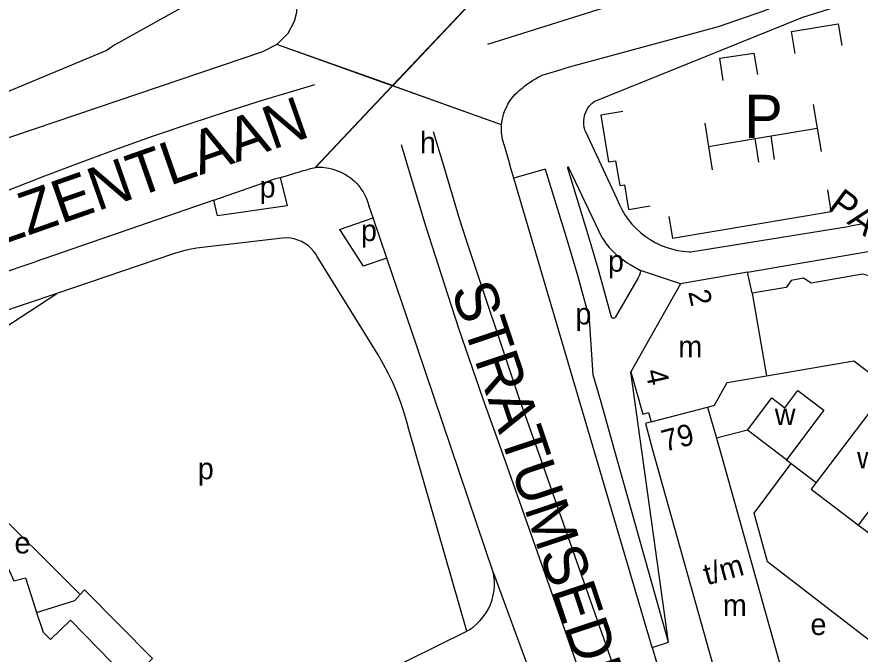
# Model space of a CAD drawing. Extents: x 161141 to 163125, y 381621 to 383200.
# Drawn here: x 161806 to 161962.7, y 382212.1 to 382330.5 of the extents above; entities that cross this region are included whole.
import ezdxf

# ---------------------------------------------------------------- set-up
doc = ezdxf.new("R2010")
doc.units = 0
for name, color, linetype in [('BLT_Basislijn', 7, 'Continuous'), ('BLT_Bebouwing', 7, 'Continuous'), ('BLT_Centroide', 7, 'Continuous'), ('BLT_Huisnummer_reeks', 7, 'Continuous'), ('BLT_Onderverdeling_panden', 7, 'Continuous'), ('BLT_Straatnaam', 7, 'Continuous'), ('BLT_Straatnaam_hoofdweg', 7, 'Continuous'), ('BLT_Tekst_parkeren', 7, 'Continuous'), ('BLT_Vlakafsluiter', 7, 'Continuous')]:
    doc.layers.add(name, color=color, linetype=linetype)

msp = doc.modelspace()

# ---------------------------------------------------------------- linework, layer by layer
at = {"layer": 'BLT_Basislijn'}
for p, q in [((161940.18, 382340.08), (161893.48, 382325.35)), ((161906.53, 382320.54), (161908.69, 382321.22)), ((161954.02, 382314.18), (161954.76, 382309.78)), ((161933.85, 382310.76), (161934.55, 382306.41)), ((161911.59, 382309.32), (161917.49, 382296.67)), ((161946.18, 382308.35), (161954.76, 382309.78)), ((161954.76, 382309.78), (161955.49, 382305.48)), ((161934.55, 382306.41), (161943.23, 382307.86)), ((161943.23, 382307.86), (161946.18, 382308.35)), ((161943.9, 382303.51), (161943.23, 382307.86)), ((161946.8, 382303.99), (161946.18, 382308.35)), ((161896.48, 382306.85), (161897.6, 382303.01)), ((161934.55, 382306.41), (161935.24, 382302.07)), ((161898.34, 382300.52), (161897.6, 382303.01)), ((161908.3, 382302.46), (161908.31, 382302.41)), ((161904.18, 382302.21), (161898.34, 382300.52)), ((161914.78, 382289.4), (161908.59, 382302.42)), ((161854.91, 382300.62), (161856.21, 382295.39)), ((161924.08, 382213.31), (161898.34, 382300.52)), ((161842.56, 382296.43), (161809.35, 382284.99)), ((161843.29, 382293.52), (161842.56, 382296.43)), ((161856.21, 382295.39), (161843.29, 382293.52)), ((161865.97, 382290.99), (161872.19, 382293.11)), ((161931.22, 382286.81), (161960.87, 382291.6)), ((161963.33, 382292.05), (161960.87, 382291.6)), ((161865.97, 382290.99), (161870.33, 382284.17)), ((161941.81, 382283.04), (161966.62, 382287.31)), ((161874.72, 382285.67), (161870.33, 382284.17)), ((161770.9, 382271.87), (161809.35, 382284.99)), ((161919.97, 382284.49), (161921.9, 382283.36)), ((161929.35, 382280.89), (161921.9, 382283.36)), ((161921.45, 382282), (161917.17, 382274.64)), ((161813.37, 382279.08), (161782.6, 382268.66)), ((161941.76, 382253.66), (161936.01, 382252.18)), ((161949.01, 382248.17), (161949.93, 382247.46)), ((161949.93, 382247.46), (161954.56, 382243.93)), ((161962.44, 382236.04), (161967.99, 382231.82)), ((161924.08, 382213.31), (161927.07, 382214.26))]:
    msp.add_line(p, q, dxfattribs=at)
for points in [[(161908.69, 382321.22), (161936.4, 382328.72), (161945.01, 382331.67), (161952.31, 382334.78), (162029.12, 382358.63), (162066.74, 382371.68)], [(161793.69, 382312.24), (161822.54, 382324.21), (161823.81, 382325.1), (161843.74, 382336.23), (161846.45, 382340.89), (161847.52, 382345.91), (161849.28, 382355.23)], [(161913.27, 382314.74), (161952.05, 382330.4), (162030.21, 382354.86)], [(161854.31, 382325.37), (161856.37, 382327.47), (161857.59, 382329.71), (161858, 382331.34), (161858.1, 382333.18), (161857.49, 382336.44), (161856.39, 382341.05)], [(161950.63, 382323.7), (161949.94, 382327.79), (161958.64, 382329.2), (161959.34, 382325.15)], [(161854.27, 382325.33), (161851.62, 382323.99), (161789.94, 382303.1)], [(161854.27, 382325.33), (161854.31, 382325.37)], [(161937.24, 382318.66), (161936.65, 382322.82), (161942.96, 382323.76), (161943.62, 382319.78)], [(161903.5, 382319.58), (161903.64, 382319.64), (161906.53, 382320.54)], [(161900.06, 382317.37), (161900.41, 382317.67), (161900.89, 382318.02), (161901.37, 382318.36), (161901.84, 382318.66), (161902.35, 382318.97), (161902.9, 382319.28), (161903.27, 382319.47), (161903.5, 382319.58)], [(161771.61, 382284.21), (161778.13, 382287.19), (161784.68, 382290.09), (161791.26, 382292.92), (161797.88, 382295.68), (161804.52, 382298.36), (161811.2, 382300.97), (161817.9, 382303.51), (161824.63, 382305.97), (161831.39, 382308.35), (161838.18, 382310.66), (161844.99, 382312.89), (161851.82, 382315.05), (161858.68, 382317.13), (161861.33, 382317.91)], [(161896.05, 382310.45), (161896.12, 382311), (161896.22, 382311.55), (161896.34, 382312.01), (161896.5, 382312.56), (161896.72, 382313.18), (161897.02, 382313.79), (161897.25, 382314.27), (161897.53, 382314.73), (161897.79, 382315.11), (161898.1, 382315.51), (161898.54, 382316.03), (161898.94, 382316.44), (161899.36, 382316.83), (161899.74, 382317.13), (161900.06, 382317.37)], [(161911.59, 382309.32), (161911.43, 382309.91), (161911.34, 382310.52), (161911.33, 382311.14), (161911.4, 382311.75), (161911.55, 382312.35), (161911.77, 382312.92), (161912.07, 382313.46), (161912.43, 382313.96), (161912.86, 382314.4), (161913.27, 382314.74)], [(161918.58, 382312.92), (161914.53, 382312.22), (161915.97, 382303.55), (161917.25, 382303.75), (161918.05, 382299.16), (161918.93, 382299.3), (161919.69, 382294.68), (161923.72, 382295.34)], [(161896.48, 382306.85), (161896.4, 382307.12), (161896.26, 382307.71), (161896.15, 382308.23), (161896.08, 382308.91), (161896.05, 382309.49), (161896.04, 382309.98), (161896.05, 382310.4)], [(161896.05, 382310.4), (161896.05, 382310.45)], [(161883.36, 382309.21), (161885.06, 382303.48), (161887.07, 382296.79), (161888.2, 382293.02), (161889.48, 382288.96), (161899.24, 382259.86), (161902.99, 382249.27), (161918.37, 382205.49)], [(161877.43, 382306.78), (161878.92, 382301.72), (161882.02, 382291.49), (161885.45, 382280.68), (161888.07, 382272.65), (161892.61, 382259.48), (161895.97, 382250), (161905.29, 382223.68), (161911.44, 382206.26), (161912.52, 382203.24)], [(161854.91, 382300.62), (161856.09, 382300.93), (161856.63, 382301.12), (161857.29, 382301.33), (161857.79, 382301.5), (161858.49, 382301.71), (161859.18, 382301.92), (161859.84, 382302.09), (161860.57, 382302.29), (161861.16, 382302.43), (161861.44, 382302.5)], [(161861.44, 382302.5), (161861.51, 382302.51)], [(161861.51, 382302.51), (161861.69, 382302.53), (161862.2, 382302.54), (161862.87, 382302.53), (161863.52, 382302.44), (161863.97, 382302.37), (161864.5, 382302.25), (161865.05, 382302.07), (161865.4, 382301.94)], [(161908.59, 382302.42), (161908.57, 382302.48), (161908.55, 382302.5), (161908.54, 382302.53), (161908.51, 382302.55), (161908.48, 382302.56), (161908.44, 382302.56), (161908.4, 382302.56), (161908.36, 382302.54), (161908.33, 382302.52), (161908.31, 382302.49), (161908.3, 382302.46)], [(161865.4, 382301.94), (161865.78, 382301.8), (161866.19, 382301.63), (161866.69, 382301.38), (161867.16, 382301.12), (161867.52, 382300.87), (161867.9, 382300.61), (161868.33, 382300.27), (161868.78, 382299.88), (161869.14, 382299.52), (161869.45, 382299.16)], [(161904.18, 382302.21), (161908.26, 382288.9), (161910.1, 382282.68), (161912.43, 382274.29)], [(161908.31, 382302.41), (161912.09, 382290.05), (161913.95, 382283.78), (161916.46, 382274.72)], [(161842.56, 382296.43), (161852.85, 382300.04), (161853.87, 382300.37), (161854.91, 382300.62)], [(161869.45, 382299.16), (161869.76, 382298.79), (161870.06, 382298.36), (161870.33, 382297.96), (161870.61, 382297.45), (161870.85, 382296.97), (161871.03, 382296.55), (161871.24, 382296.01), (161871.41, 382295.41)], [(161927.17, 382293.36), (161927.85, 382289.34), (161957.33, 382294.34), (161956.69, 382298.34)], [(161917.49, 382296.67), (161917.92, 382295.65), (161918.41, 382294.67), (161918.98, 382293.72), (161919.61, 382292.82), (161920.31, 382291.97), (161921.07, 382291.16), (161921.88, 382290.42), (161922.74, 382289.74), (161923.66, 382289.12), (161924.61, 382288.57), (161925.6, 382288.09), (161926.63, 382287.68), (161927.68, 382287.35), (161928.75, 382287.1), (161929.84, 382286.92), (161930.94, 382286.82), (161931.22, 382286.81)], [(161872.19, 382293.11), (161871.41, 382295.41)], [(161874.72, 382285.67), (161872.19, 382293.11)], [(161889.62, 382216.36), (161878.85, 382253.8), (161878.48, 382255.26), (161877.93, 382257.12), (161877.31, 382258.96), (161876.62, 382260.77), (161875.84, 382262.55), (161875, 382264.29), (161874.08, 382266), (161873.1, 382267.67), (161861.77, 382285.96), (161861.54, 382286.36), (161861.12, 382286.95), (161860.64, 382287.49), (161860.1, 382287.97), (161859.51, 382288.39), (161858.88, 382288.74), (161858.21, 382289.02), (161857.52, 382289.22), (161856.81, 382289.35), (161856.09, 382289.4), (161855.37, 382289.37), (161839.34, 382287.49), (161838.03, 382287.26), (161836.73, 382286.96), (161835.45, 382286.57), (161834.9, 382286.38), (161813.37, 382279.08)], [(161914.78, 382289.4), (161915.08, 382288.97), (161915.52, 382288.32), (161916.1, 382287.64), (161916.83, 382286.89), (161917.58, 382286.16), (161918.41, 382285.51), (161919.43, 382284.8), (161919.97, 382284.49)], [(161894.55, 382227.12), (161880.38, 382269.13), (161874.72, 382285.67)], [(161921.9, 382283.36), (161921.84, 382282.92), (161921.71, 382282.51), (161921.45, 382282)], [(161799.51, 382241.21), (161791.52, 382254.7), (161790.8, 382256.18), (161790.41, 382257.59), (161790.23, 382259.1), (161790.33, 382260.52), (161790.62, 382261.9), (161791.11, 382263.16), (161792.02, 382264.63), (161793.43, 382266.08), (161813.37, 382279.08)], [(161913.08, 382263.94), (161912.43, 382274.29)], [(161916.46, 382274.72), (161916.53, 382274.64), (161916.59, 382274.59), (161916.66, 382274.55), (161916.73, 382274.53), (161916.81, 382274.52), (161916.9, 382274.52), (161917, 382274.54), (161917.09, 382274.57), (161917.17, 382274.64)], [(161917.12, 382249.78), (161914.57, 382258.9), (161913.08, 382263.94)], [(161927.07, 382214.26), (161917.12, 382249.78)], [(161974.35, 382213.48), (161969.59, 382216.89), (161966.66, 382212.94), (161945.48, 382229.23), (161943.05, 382238.25), (161949.93, 382247.46)], [(161799.51, 382241.21), (161817.74, 382223.13)], [(161889.62, 382216.36), (161890.02, 382216.59), (161890.76, 382217.1), (161891.45, 382217.67), (161892.09, 382218.29), (161892.67, 382218.98), (161893.18, 382219.71), (161893.63, 382220.48), (161894.01, 382221.29), (161894.31, 382222.13), (161894.53, 382223), (161894.68, 382223.88), (161894.75, 382224.77), (161894.74, 382225.66), (161894.65, 382226.55), (161894.55, 382227.12)], [(161809.64, 382219.82), (161816.77, 382222.02), (161817.74, 382223.13)], [(161817.74, 382223.13), (161818.53, 382224.04), (161831.21, 382211.26), (161829.68, 382209.79), (161851.35, 382188.38), (161869.69, 382206.17), (161873.3, 382208.26), (161889.62, 382216.36)], [(161924.08, 382213.31), (161925.57, 382208.25)]]:
    msp.add_lwpolyline(points, dxfattribs=at)
at = {"layer": 'BLT_Bebouwing'}
for p, q in [((161934.37, 382257.94), (161935.65, 382258.3)), ((161934.37, 382257.94), (161936.01, 382252.18)), ((161955.99, 382257.39), (161949.01, 382248.17)), ((161964.53, 382257.1), (161954.56, 382243.93)), ((161949.01, 382248.17), (161941.76, 382253.66))]:
    msp.add_line(p, q, dxfattribs=at)
for points in [[(161941.81, 382283.04), (161929.35, 382280.89), (161920.1, 382264.51), (161922.31, 382256.66), (161923.36, 382256.96), (161923.87, 382255.21)], [(161942.66, 382279.14), (161941.81, 382283.04)], [(161986.45, 382272.09), (161984.12, 382269.04), (161979.05, 382272.85), (161978.75, 382274.5), (161976.92, 382275.9), (161975.29, 382275.66), (161967.51, 382281.59), (161963.19, 382282.65), (161953.6, 382280.99), (161952.2, 382281.92), (161949.93, 382281.52), (161948.95, 382280.21), (161942.66, 382279.14)], [(161945.3, 382263.8), (161961.55, 382266.57), (161975.1, 382256.28), (161976.29, 382257.89), (161986.69, 382250), (161997.37, 382241.91)], [(161935.65, 382258.3), (161937.98, 382262.56), (161945.3, 382263.8)], [(161941.76, 382253.66), (161946.3, 382259.66), (161948.7, 382257.85), (161951.13, 382261.06), (161955.99, 382257.39)], [(161962.44, 382236.04), (161973.33, 382250.43), (161964.53, 382257.1)], [(161923.87, 382255.21), (161922.8, 382254.9), (161924.12, 382250), (161936.12, 382207.22), (161932.73, 382206.27)], [(161936.01, 382252.18), (161936.64, 382250), (161947.76, 382210.42)], [(161954.56, 382243.93), (161953.63, 382242.71), (161962.44, 382236.04)], [(161795.86, 382238.55), (161800.11, 382231.88), (161802.29, 382232.44), (161805.39, 382225.71), (161807.55, 382226.26), (161809.06, 382221.61), (161809.64, 382219.82)], [(161809.64, 382219.82), (161810.83, 382216.16), (161812.2, 382214.76), (161815.92, 382218.4), (161826.12, 382207.96), (161825.04, 382206.91), (161845.24, 382186.22), (161833.86, 382175.11), (161827.89, 382181.22), (161818.28, 382171.83), (161824.1, 382165.86), (161805.66, 382147.5)]]:
    msp.add_lwpolyline(points, dxfattribs=at)
at = {"layer": 'BLT_Onderverdeling_panden'}
for p, q in [((161942.66, 382279.14), (161945.3, 382263.8)), ((161923.87, 382255.21), (161934.37, 382257.94))]:
    msp.add_line(p, q, dxfattribs=at)
at = {"layer": 'BLT_Vlakafsluiter'}
for p, q in [((161875.78, 382317.7), (161895.42, 382338.5)), ((161875.83, 382317.68), (161895.52, 382338.54)), ((161875.74, 382317.66), (161854.27, 382325.33)), ((161875.78, 382317.7), (161854.31, 382325.37)), ((161861.44, 382302.5), (161875.74, 382317.66)), ((161861.51, 382302.51), (161875.79, 382317.64)), ((161896.05, 382310.4), (161875.79, 382317.64)), ((161896.05, 382310.45), (161875.83, 382317.68)), ((161927.07, 382214.26), (161920.1, 382264.51)), ((161894.55, 382227.12), (161904.49, 382200.16))]:
    msp.add_line(p, q, dxfattribs=at)

# ---------------------------------------------------------------- texts
at = {"layer": 'BLT_Centroide'}
for s, p in [('h', (161880.9, 382305.11)), ('p', (161851.09, 382296.9)), ('p', (161869.93, 382288.82)), ('p', (161915.84, 382283.13)), ('p', (161909.79, 382273.33)), ('m', (161928.92, 382267.23)), ('w', (161946.85, 382254.62)), ('w', (161962.15, 382246.56)), ('p', (161839.6, 382244.56)), ('e', (161805.53, 382230.77)), ('m', (161937.2, 382219.17)), ('e', (161953.49, 382215.61))]:
    msp.add_text(s, height=4, dxfattribs=at).set_placement(p)
at = {"layer": 'BLT_Huisnummer_reeks'}
for s, rotation, p in [('2', 282.3343, (161930.75, 382279.38)), ('4', 282.3343, (161922.77, 382264.65)), ('79', 14.5638, (161926.4, 382249.65)), ('t/m', 15.6542, (161934.26, 382224.85))]:
    msp.add_text(s, height=4, rotation=rotation, dxfattribs=at).set_placement(p)
at = {"layer": 'BLT_Straatnaam'}
msp.add_text('PASTOOR HARKXPLEIN', height=5, rotation=323.4931, dxfattribs=at).set_placement((161956.53, 382294.85))
at = {"layer": 'BLT_Straatnaam_hoofdweg'}
for s, rotation, p in [('ELZENTLAAN', 19.3233, (161795.66, 382285.49)), ('STRATUMSEDIJK', 288.5265, (161886.64, 382279.78))]:
    msp.add_text(s, height=8, rotation=rotation, dxfattribs=at).set_placement(p)
at = {"layer": 'BLT_Tekst_parkeren'}
msp.add_text('P', height=8, dxfattribs=at).set_placement((161941.21, 382308))

doc.saveas('drawing.dxf')
